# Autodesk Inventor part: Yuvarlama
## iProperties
Company: Autodesk, Inc.
Shininess: 64.0
Length Units: 11269
Angle Units: 11279
Time Units: 11290
Mass Units: 11283
Length Display Precision: 3
Angle Display Precision: 2
Compacted: True
Part Number: Yuvarlama
Document SubType Name: Modeling
Created: 2003-11
Catalog Web Link: www.autodesk.com
Vendor: Autodesk, Inc.
Designer: Administrator
Manufacturer: Standard
Standards Organization: Custom
Density: 1 g/cm^3
Density: 0.0
Volumn: 0.0
Area: 0.0
PropertySet Name: Model Information
Control State: 0
Master: False
Checked Out: False
Author: Administrator
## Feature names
1. Extrusion1
2. Extrusion2
3. Extrusion3
4. Extrusion4
5. Mirror1
